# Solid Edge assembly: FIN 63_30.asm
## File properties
Title: Zylinder
Author: bmolnar
Template: iso assembly.asm
Last saved by: bmolnar
Revision: 9
Application: Solid Edge
Username: bmolnar
Dokumentum tartalom típus: 1
Document Number: FIN 63/30
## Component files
Kit_1.par
Profilrohr.par
Kit_2.par
Kolbenstange.par
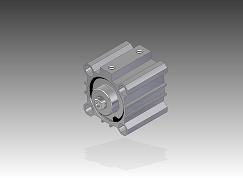
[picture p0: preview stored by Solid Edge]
